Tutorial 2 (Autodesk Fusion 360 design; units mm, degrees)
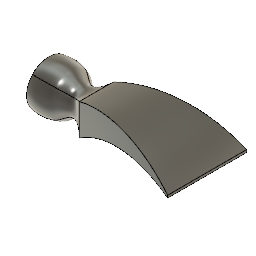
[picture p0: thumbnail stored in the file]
sketch "Sketch2" plane through (0, 0, 0) normal (1, 0, 0) x axis (0, 1, 0)
  circle C1 centre (0, 0) radius 42.5
  point P1 (0, 0)
  point P2 (0, 0)
  coincident P1 P2
  dimension "d1" diameter C1 = 85
work_plane "WorkPlane1" AlongDistance 40
sketch "Sketch3" plane through (40, 0, 0) normal (1, 0, 0) x axis (0, 1, 0)
  circle C1 centre (0, 0) radius 40
  point P1 (0, 0)
  point P2 (0, 0)
  coincident P1 P2
  dimension "d3" diameter C1 = 80
work_plane "WorkPlane2" AlongDistance 65
sketch "Sketch4" plane through (65, 0, 0) normal (1, 0, 0) x axis (0, 1, 0)
  circle C1 centre (0, 0) radius 25
  point P1 (0, 0)
  point P2 (0, 0)
  coincident P1 P2
  dimension "d5" diameter C1 = 50
work_plane "WorkPlane3" AlongDistance 90
sketch "Sketch5" plane through (90, 0, 0) normal (1, 0, 0) x axis (0, 1, 0)
  line L1 (-32.5, 30) -> (32.5, 30)
  line L2 (-32.5, -30) -> (-32.5, 30)
  line L3 (32.5, -30) -> (-32.5, -30)
  line L4 (32.5, 30) -> (32.5, -30)
  line L5 (-32.5, -30) -> (32.5, 30)
  line L6 (32.5, -30) -> (-32.5, 30)
  point P6 (0, 0)
  point P1 (0, 0)
  point P4 (-32.5, -30)
  point P5 (32.5, -30)
  point P2 (32.5, 30)
  horizontal L1
  perpendicular L1 L2
  parallel L1 L3
  parallel L2 L4
  coincident L5 P6
  coincident L6 P6
  coincident P1 P6
  dimension "d7" distance P4 P5 = 65
  dimension "d8" distance P2 P5 = 60
loft "Loft1"
work_plane "WorkPlane4" AlongDistance 210
sketch "Sketch6" plane through (300, 0, 0) normal (1, 0, 0) x axis (0, 1, 0)
  line L1 (-75, 2.5) -> (75, 2.5)
  line L2 (-75, -2.5) -> (-75, 2.5)
  line L3 (75, -2.5) -> (-75, -2.5)
  line L4 (75, 2.5) -> (75, -2.5)
  line L5 (-75, -2.5) -> (75, 2.5)
  line L6 (75, -2.5) -> (-75, 2.5)
  point P6 (0, 0)
  point P1 (0, 0)
  point P4 (-75, -2.5)
  point P5 (75, -2.5)
  point P2 (75, 2.5)
  horizontal L1
  perpendicular L1 L2
  parallel L1 L3
  parallel L2 L4
  coincident L5 P6
  coincident L6 P6
  coincident P1 P6
  dimension "d10" distance P4 P5 = 150
  dimension "d11" distance P2 P5 = 5
sketch "Sketch8" plane through (0, 0, 0) normal (0, 1, 0) x axis (1, 0, 0)
  arc A1 centre (169.9614, 174.9541) radius 220 clockwise from (300, -2.5) to (90, -30)
  point P2 (90, -30)
  point P5 (90, -30)
  point P3 (300, -2.5)
  point P6 (300, -2.5)
  coincident P2 P5
  coincident P3 P6
  dimension "d12" radius A1 = 220
loft "Loft2" sketch "Sketch6"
